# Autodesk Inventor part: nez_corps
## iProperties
Shininess: 64.0
Length Units: 11269
Angle Units: 11279
Time Units: 11290
Mass Units: 11283
Length Display Precision: 3
Angle Display Precision: 2
Compacted: True
Part Number: nez_corps
Document SubType Name: Modeling
Created: 2004-05
Material: Par défaut
Designer: David
Density: 0.0
Volumn: 0.0
Area: 0.0
PropertySet Name: Model Information
Control State: 0
Master: False
Checked Out: False
Author: David
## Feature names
1. Lissage1
2. Lissage2
3. Extrusion1
4. Extrusion2
5. Extrusion3
